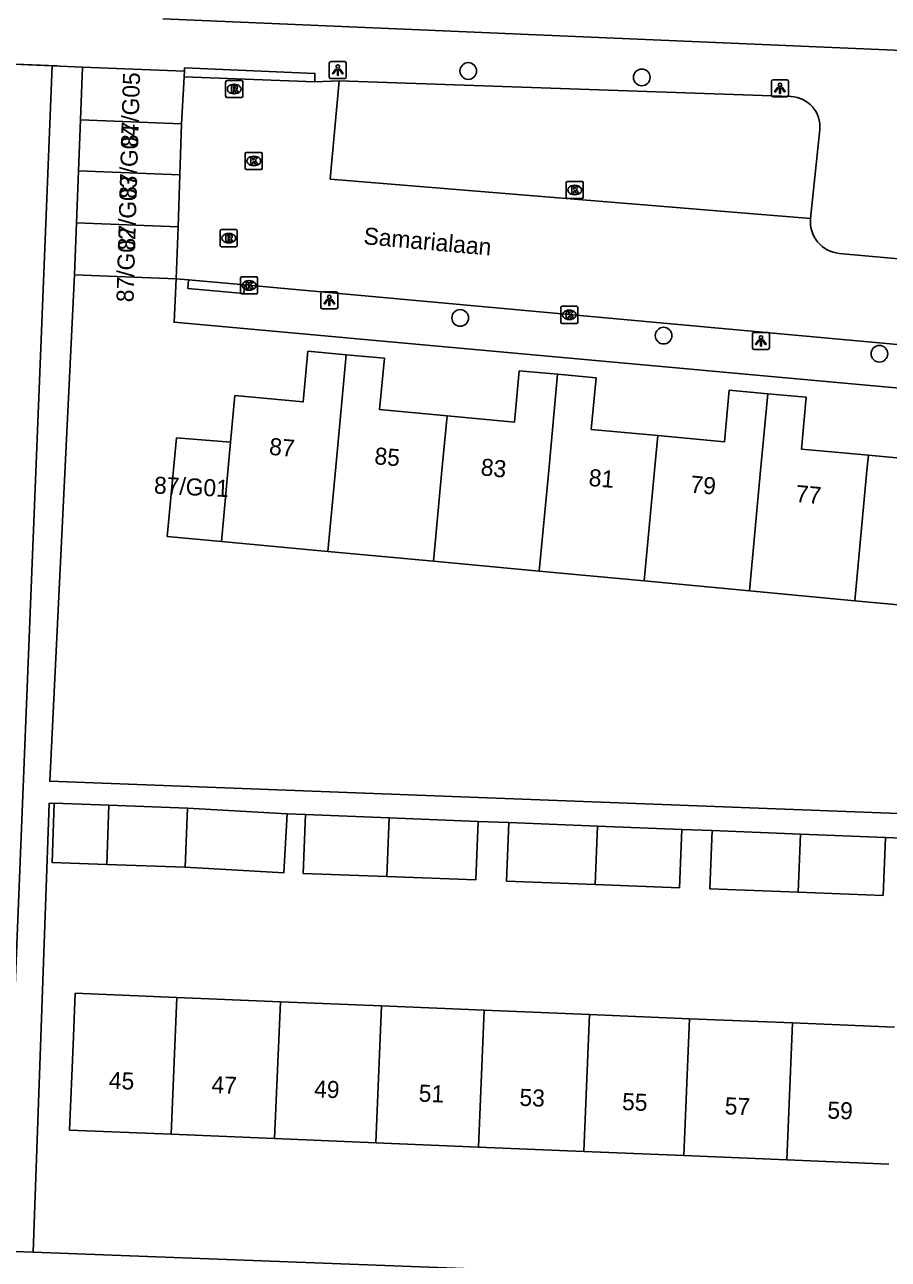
# Model space of a CAD drawing. Extents: x 161355 to 162026, y 386504 to 387459.
# Drawn here: x 161429.3 to 161480, y 386953.7 to 387026.1 of the extents above; entities that cross this region are included whole.
import ezdxf

# ---------------------------------------------------------------- set-up
doc = ezdxf.new("R2010")
doc.units = 0
for name, color, linetype in [('IMGEO_Boom', 7, 'Continuous'), ('IMGEO_Kolk', 7, 'Continuous'), ('IMGEO_Lichtpunt', 7, 'Continuous'), ('IMGEO_Muur', 7, 'Continuous'), ('IMGEO_Openbare_ruimte_label', 7, 'Continuous'), ('IMGEO_Pand', 7, 'Continuous'), ('IMGEO_Pand_nummerreeks', 7, 'Continuous'), ('IMGEO_Rijbaan_lokaal_open', 7, 'Continuous'), ('IMGEO_Rioolput', 7, 'Continuous'), ('IMGEO_Voetpad_open', 7, 'Continuous')]:
    doc.layers.add(name, color=color, linetype=linetype)

msp = doc.modelspace()

# ---------------------------------------------------------------- linework, layer by layer
at = {"layer": 'IMGEO_Boom'}
for centre in [(161455.37, 387023.422), (161465.547, 387023.046), (161454.896, 387008.942), (161466.827, 387007.904), (161479.482, 387006.842)]:
    msp.add_circle(centre, 0.489, dxfattribs=at)
at = {"layer": 'IMGEO_Kolk'}
for p, q in [((161442.286, 387017.721), (161442.286, 387018.573)), ((161442.361, 387018.647), (161443.213, 387018.647)), ((161442.774, 387018.427), (161442.799, 387018.427)), ((161443.287, 387018.573), (161443.287, 387017.721)), ((161443.213, 387017.647), (161442.361, 387017.647)), ((161442.797, 387017.867), (161442.772, 387017.867)), ((161461.114, 387016.016), (161461.114, 387016.868)), ((161461.189, 387016.942), (161462.041, 387016.942)), ((161462.115, 387016.868), (161462.115, 387016.016)), ((161461.625, 387016.162), (161461.6, 387016.162)), ((161461.602, 387016.722), (161461.627, 387016.722)), ((161462.041, 387015.942), (161461.189, 387015.942)), ((161442.01, 387010.423), (161442.01, 387011.275)), ((161442.085, 387011.349), (161442.937, 387011.349)), ((161442.498, 387011.129), (161442.523, 387011.129)), ((161443.011, 387011.275), (161443.011, 387010.423)), ((161442.937, 387010.349), (161442.085, 387010.349)), ((161442.521, 387010.569), (161442.496, 387010.569)), ((161460.795, 387008.698), (161460.795, 387009.55)), ((161460.87, 387009.624), (161461.722, 387009.624)), ((161461.796, 387009.55), (161461.796, 387008.698)), ((161461.306, 387008.844), (161461.281, 387008.844)), ((161461.283, 387009.404), (161461.308, 387009.404)), ((161461.722, 387008.624), (161460.87, 387008.624))]:
    msp.add_line(p, q, dxfattribs=at)
for points in [[(161442.286, 387017.721), (161442.286, 387018.573)], [(161442.361, 387018.647), (161443.213, 387018.647)], [(161442.607, 387018.347), (161442.73, 387018.347), (161442.73, 387018.196), (161442.86, 387018.347), (161443.024, 387018.347), (161442.878, 387018.196), (161443.031, 387017.947), (161442.879, 387017.947), (161442.794, 387018.111), (161442.73, 387018.044), (161442.73, 387017.947), (161442.607, 387017.947), (161442.607, 387018.347)], [(161443.287, 387018.573), (161443.287, 387017.721)], [(161443.213, 387017.647), (161442.361, 387017.647)], [(161461.114, 387016.016), (161461.114, 387016.868)], [(161461.189, 387016.942), (161462.041, 387016.942)], [(161462.115, 387016.868), (161462.115, 387016.016)], [(161461.435, 387016.642), (161461.558, 387016.642), (161461.558, 387016.491), (161461.688, 387016.642), (161461.852, 387016.642), (161461.706, 387016.491), (161461.859, 387016.242), (161461.707, 387016.242), (161461.622, 387016.406), (161461.558, 387016.339), (161461.558, 387016.242), (161461.435, 387016.242), (161461.435, 387016.642)], [(161462.041, 387015.942), (161461.189, 387015.942)], [(161442.01, 387010.423), (161442.01, 387011.275)], [(161442.085, 387011.349), (161442.937, 387011.349)], [(161442.331, 387011.049), (161442.454, 387011.049), (161442.454, 387010.898), (161442.584, 387011.049), (161442.748, 387011.049), (161442.602, 387010.898), (161442.755, 387010.649), (161442.603, 387010.649), (161442.518, 387010.813), (161442.454, 387010.746), (161442.454, 387010.649), (161442.331, 387010.649), (161442.331, 387011.049)], [(161443.011, 387011.275), (161443.011, 387010.423)], [(161442.937, 387010.349), (161442.085, 387010.349)], [(161460.795, 387008.698), (161460.795, 387009.55)], [(161460.87, 387009.624), (161461.722, 387009.624)], [(161461.796, 387009.55), (161461.796, 387008.698)], [(161461.116, 387009.324), (161461.239, 387009.324), (161461.239, 387009.173), (161461.369, 387009.324), (161461.533, 387009.324), (161461.387, 387009.173), (161461.54, 387008.924), (161461.388, 387008.924), (161461.303, 387009.088), (161461.239, 387009.021), (161461.239, 387008.924), (161461.116, 387008.924), (161461.116, 387009.324)], [(161461.722, 387008.624), (161460.87, 387008.624)]]:
    msp.add_lwpolyline(points, dxfattribs=at)
for centre, start, end in [((161442.363, 387018.571), 91.55205, 178.44795), ((161442.363, 387018.571), 91.55205, 178.44795), ((161443.211, 387018.571), 1.55205, 88.44795), ((161443.211, 387018.571), 1.55205, 88.44795), ((161442.363, 387017.723), 181.55205, 268.44795), ((161442.363, 387017.723), 181.55205, 268.44795), ((161443.211, 387017.723), 271.55205, 358.44795), ((161443.211, 387017.723), 271.55205, 358.44795), ((161461.191, 387016.866), 91.55205, 178.44795), ((161461.191, 387016.866), 91.55205, 178.44795), ((161462.039, 387016.866), 1.55205, 88.44795), ((161462.039, 387016.866), 1.55205, 88.44795), ((161461.191, 387016.018), 181.55205, 268.44795), ((161461.191, 387016.018), 181.55205, 268.44795), ((161462.039, 387016.018), 271.55205, 358.44795), ((161462.039, 387016.018), 271.55205, 358.44795), ((161442.087, 387011.273), 91.55205, 178.44795), ((161442.087, 387011.273), 91.55205, 178.44795), ((161442.935, 387011.273), 1.55205, 88.44795), ((161442.935, 387011.273), 1.55205, 88.44795), ((161442.087, 387010.425), 181.55205, 268.44795), ((161442.087, 387010.425), 181.55205, 268.44795), ((161442.935, 387010.425), 271.55205, 358.44795), ((161442.935, 387010.425), 271.55205, 358.44795), ((161460.872, 387009.548), 91.55205, 178.44795), ((161460.872, 387009.548), 91.55205, 178.44795), ((161461.72, 387009.548), 1.55205, 88.44795), ((161461.72, 387009.548), 1.55205, 88.44795), ((161460.872, 387008.7), 181.55205, 268.44795), ((161460.872, 387008.7), 181.55205, 268.44795), ((161461.72, 387008.7), 271.55205, 358.44795), ((161461.72, 387008.7), 271.55205, 358.44795)]:
    msp.add_arc(centre, 0.0765, start, end, dxfattribs=at)
for centre, major_axis, ratio, start_param, end_param in [((161442.773, 387018.147), (-0.387, 0.002), 0.722429, 4.712389, 7.853982), ((161442.798, 387018.147), (-0.39, 0.002), 0.717154, 1.570796, 4.712389), ((161461.601, 387016.442), (-0.387, 0.002), 0.722429, 4.712389, 7.853982), ((161461.626, 387016.442), (-0.39, 0.002), 0.717154, 1.570796, 4.712389), ((161442.497, 387010.849), (-0.387, 0.002), 0.722429, 4.712389, 7.853982), ((161442.522, 387010.849), (-0.39, 0.002), 0.717154, 1.570796, 4.712389), ((161461.282, 387009.124), (-0.387, 0.002), 0.722429, 4.712389, 7.853982), ((161461.307, 387009.124), (-0.39, 0.002), 0.717154, 1.570796, 4.712389)]:
    msp.add_ellipse(centre, major_axis=major_axis, ratio=ratio, start_param=start_param, end_param=end_param, dxfattribs=at)
at = {"layer": 'IMGEO_Lichtpunt'}
for p, q in [((161447.217, 387023.882), (161447.217, 387023.075)), ((161447.217, 387023.882), (161447.217, 387023.075)), ((161448.119, 387023.977), (161447.311, 387023.977)), ((161448.119, 387023.977), (161447.311, 387023.977)), ((161448.213, 387023.075), (161448.213, 387023.882)), ((161448.213, 387023.075), (161448.213, 387023.882)), ((161447.311, 387022.981), (161448.119, 387022.981)), ((161447.311, 387022.981), (161448.119, 387022.981)), ((161473.153, 387022.815), (161473.153, 387022.008)), ((161473.153, 387022.815), (161473.153, 387022.008)), ((161474.055, 387022.91), (161473.247, 387022.91)), ((161474.055, 387022.91), (161473.247, 387022.91)), ((161474.149, 387022.008), (161474.149, 387022.815)), ((161474.149, 387022.008), (161474.149, 387022.815)), ((161473.247, 387021.914), (161474.055, 387021.914)), ((161473.247, 387021.914), (161474.055, 387021.914)), ((161446.721, 387010.38), (161446.721, 387009.573)), ((161446.721, 387010.38), (161446.721, 387009.573)), ((161447.623, 387010.475), (161446.815, 387010.475)), ((161447.623, 387010.475), (161446.815, 387010.475)), ((161447.717, 387009.573), (161447.717, 387010.38)), ((161447.717, 387009.573), (161447.717, 387010.38)), ((161446.815, 387009.479), (161447.623, 387009.479)), ((161446.815, 387009.479), (161447.623, 387009.479)), ((161472.941, 387008.097), (161472.133, 387008.097)), ((161472.941, 387008.097), (161472.133, 387008.097)), ((161472.039, 387008.002), (161472.039, 387007.195)), ((161472.039, 387008.002), (161472.039, 387007.195)), ((161473.035, 387007.195), (161473.035, 387008.002)), ((161473.035, 387007.195), (161473.035, 387008.002)), ((161472.133, 387007.101), (161472.941, 387007.101)), ((161472.133, 387007.101), (161472.941, 387007.101))]:
    msp.add_line(p, q, dxfattribs=at)
for points in [[(161447.591, 387023.546), (161447.63, 387023.518), (161447.442, 387023.256), (161447.404, 387023.283), (161447.591, 387023.546)], [(161447.693, 387023.498), (161447.74, 387023.498), (161447.74, 387023.176), (161447.693, 387023.176), (161447.693, 387023.498)], [(161447.803, 387023.518), (161447.841, 387023.545), (161448.028, 387023.283), (161447.989, 387023.255), (161447.803, 387023.518)], [(161473.527, 387022.479), (161473.566, 387022.451), (161473.378, 387022.189), (161473.34, 387022.216), (161473.527, 387022.479)], [(161473.629, 387022.431), (161473.676, 387022.431), (161473.676, 387022.109), (161473.629, 387022.109), (161473.629, 387022.431)], [(161473.739, 387022.451), (161473.777, 387022.478), (161473.964, 387022.216), (161473.925, 387022.188), (161473.739, 387022.451)], [(161447.095, 387010.044), (161447.134, 387010.016), (161446.946, 387009.754), (161446.908, 387009.781), (161447.095, 387010.044)], [(161447.197, 387009.996), (161447.244, 387009.996), (161447.244, 387009.674), (161447.197, 387009.674), (161447.197, 387009.996)], [(161447.307, 387010.016), (161447.345, 387010.043), (161447.532, 387009.781), (161447.493, 387009.753), (161447.307, 387010.016)], [(161472.413, 387007.666), (161472.452, 387007.638), (161472.264, 387007.376), (161472.226, 387007.403), (161472.413, 387007.666)], [(161472.515, 387007.618), (161472.562, 387007.618), (161472.562, 387007.296), (161472.515, 387007.296), (161472.515, 387007.618)], [(161472.625, 387007.638), (161472.663, 387007.665), (161472.85, 387007.403), (161472.811, 387007.375), (161472.625, 387007.638)]]:
    msp.add_lwpolyline(points, dxfattribs=at)
for centre in [(161447.716, 387023.68), (161473.652, 387022.613), (161447.22, 387010.178), (161472.538, 387007.8)]:
    msp.add_circle(centre, 0.0994, dxfattribs=at)
for centre, start, end in [((161447.311, 387023.882), 90, 180), ((161447.311, 387023.882), 90, 180), ((161448.119, 387023.882), 0, 90), ((161448.119, 387023.882), 0, 90), ((161447.311, 387023.075), 180, 270), ((161447.311, 387023.075), 180, 270), ((161448.119, 387023.075), 270, 0), ((161448.119, 387023.075), 270, 360), ((161473.247, 387022.815), 90, 180), ((161473.247, 387022.815), 90, 180), ((161474.055, 387022.815), 0, 90), ((161474.055, 387022.815), 0, 90), ((161473.247, 387022.008), 180, 270), ((161473.247, 387022.008), 180, 270), ((161474.055, 387022.008), 270, 0), ((161474.055, 387022.008), 270, 360), ((161446.815, 387010.38), 90, 180), ((161446.815, 387010.38), 90, 180), ((161447.623, 387010.38), 0, 90), ((161447.623, 387010.38), 0, 90), ((161446.815, 387009.573), 180, 270), ((161446.815, 387009.573), 180, 270), ((161447.623, 387009.573), 270, 0), ((161447.623, 387009.573), 270, 360), ((161472.133, 387008.002), 90, 180), ((161472.133, 387008.002), 90, 180), ((161472.941, 387008.002), 0, 90), ((161472.941, 387008.002), 0, 90), ((161472.133, 387007.195), 180, 270), ((161472.133, 387007.195), 180, 270), ((161472.941, 387007.195), 270, 0), ((161472.941, 387007.195), 270, 360)]:
    msp.add_arc(centre, 0.0946, start, end, dxfattribs=at)
at = {"layer": 'IMGEO_Muur'}
msp.add_lwpolyline([(161431.241, 387023.718), (161424.947, 387023.983)], dxfattribs=at)
at = {"layer": 'IMGEO_Pand'}
for points in [[(161432.74, 387023.655), (161432.618, 387020.553)], [(161438.717, 387023.42), (161432.74, 387023.655)], [(161438.717, 387023.42), (161438.699, 387023.089)], [(161438.699, 387023.089), (161438.547, 387020.324)], [(161432.618, 387020.553), (161432.501, 387017.566)], [(161432.618, 387020.553), (161438.547, 387020.324)], [(161438.547, 387020.324), (161438.453, 387017.332)], [(161432.381, 387014.522), (161432.501, 387017.566)], [(161432.501, 387017.566), (161438.453, 387017.332)], [(161438.453, 387017.332), (161438.358, 387014.287)], [(161432.381, 387014.522), (161432.262, 387011.478)], [(161438.358, 387014.287), (161432.381, 387014.522)], [(161438.358, 387014.287), (161438.239, 387011.243)], [(161432.262, 387011.478), (161438.239, 387011.243)], [(161441.431, 387001.649), (161441.685, 387004.394), (161445.688, 387004.023), (161445.963, 387006.992), (161448.208, 387006.784)], [(161448.208, 387006.784), (161447.574, 387000), (161447.13, 386995.256)], [(161454.125, 387003.206), (161450.171, 387003.572), (161450.45, 387006.576), (161448.208, 387006.784)], [(161460.612, 387005.637), (161458.361, 387005.845), (161458.082, 387002.839), (161454.125, 387003.206)], [(161459.533, 386994.096), (161460.085, 387000), (161460.612, 387005.637)], [(161466.49, 387002.046), (161462.585, 387002.408), (161462.865, 387005.428), (161460.612, 387005.637)], [(161466.49, 387002.046), (161470.397, 387001.684), (161470.678, 387004.71), (161472.935, 387004.5)], [(161472.935, 387004.5), (161472.515, 387000), (161471.855, 386992.943)], [(161472.935, 387004.5), (161475.192, 387004.291), (161474.91, 387001.252), (161478.838, 387000.888)], [(161453.328, 386994.676), (161453.826, 387000), (161454.125, 387003.206)], [(161485.285, 387003.307), (161483.042, 387003.514), (161482.765, 387000.524), (161478.838, 387000.888)], [(161440.89, 386995.839), (161437.709, 386996.137), (161438.259, 387001.907), (161441.431, 387001.649)], [(161441.431, 387001.649), (161440.89, 386995.839)], [(161465.693, 386993.519), (161466.299, 387000), (161466.49, 387002.046)], [(161478.838, 387000.888), (161478.755, 387000), (161478.041, 386992.364)], [(161447.13, 386995.256), (161440.89, 386995.839)], [(161447.13, 386995.256), (161453.328, 386994.676)], [(161453.328, 386994.676), (161459.533, 386994.096)], [(161459.533, 386994.096), (161465.693, 386993.519)], [(161471.855, 386992.943), (161465.693, 386993.519)], [(161478.041, 386992.364), (161471.855, 386992.943)], [(161478.041, 386992.364), (161484.208, 386991.788)], [(161434.159, 386976.895), (161430.959, 386977.014), (161431.087, 386980.484)], [(161431.087, 386980.484), (161434.288, 386980.365)], [(161434.288, 386980.365), (161434.159, 386976.895)], [(161434.288, 386980.365), (161438.896, 386980.191)], [(161438.753, 386976.737), (161438.896, 386980.191)], [(161444.745, 386979.866), (161444.553, 386976.414), (161438.753, 386976.737)], [(161438.896, 386980.191), (161444.745, 386979.866)], [(161445.828, 386979.823), (161445.685, 386976.371), (161450.594, 386976.186)], [(161445.828, 386979.823), (161450.736, 386979.63)], [(161450.736, 386979.63), (161450.594, 386976.186)], [(161450.594, 386976.186), (161455.805, 386975.989), (161455.946, 386979.424)], [(161455.946, 386979.424), (161450.736, 386979.63)], [(161457.753, 386979.353), (161457.611, 386975.92), (161462.805, 386975.724)], [(161462.946, 386979.148), (161457.753, 386979.353)], [(161462.946, 386979.148), (161462.805, 386975.724)], [(161467.901, 386978.953), (161462.946, 386979.148)], [(161462.805, 386975.724), (161467.76, 386975.536), (161467.901, 386978.953)], [(161469.673, 386978.883), (161469.531, 386975.469), (161474.71, 386975.274)], [(161474.851, 386978.679), (161469.673, 386978.883)], [(161474.851, 386978.679), (161474.71, 386975.274)], [(161474.71, 386975.274), (161479.704, 386975.085), (161479.844, 386978.482)], [(161479.844, 386978.482), (161474.851, 386978.679)], [(161434.159, 386976.895), (161438.753, 386976.737)], [(161438.272, 386969.101), (161432.314, 386969.348), (161432.188, 386966.317), (161431.981, 386961.321), (161437.939, 386961.074)], [(161437.939, 386961.074), (161438.272, 386969.101)], [(161444.345, 386968.849), (161438.272, 386969.101)], [(161444.345, 386968.849), (161444.012, 386960.822)], [(161450.279, 386968.603), (161444.345, 386968.849)], [(161449.946, 386960.576), (161450.279, 386968.603)], [(161450.279, 386968.603), (161456.306, 386968.353)], [(161456.306, 386968.353), (161455.973, 386960.326)], [(161462.488, 386968.097), (161456.306, 386968.353)], [(161462.155, 386960.07), (161462.488, 386968.097)], [(161468.353, 386967.854), (161462.488, 386968.097)], [(161468.353, 386967.854), (161468.021, 386959.826)], [(161474.393, 386967.604), (161468.353, 386967.854)], [(161474.061, 386959.576), (161474.393, 386967.604)], [(161480.376, 386967.356), (161474.393, 386967.604)], [(161437.939, 386961.074), (161444.012, 386960.822)], [(161444.012, 386960.822), (161449.946, 386960.576)], [(161455.973, 386960.326), (161449.946, 386960.576)], [(161455.973, 386960.326), (161462.155, 386960.07)], [(161462.155, 386960.07), (161468.021, 386959.826)], [(161468.021, 386959.826), (161474.061, 386959.576)], [(161474.061, 386959.576), (161480.043, 386959.328)]]:
    msp.add_lwpolyline(points, dxfattribs=at)
at = {"layer": 'IMGEO_Rijbaan_lokaal_open'}
for points in [[(161446.36, 387022.778), (161438.699, 387023.089)], [(161447.79, 387022.848), (161446.36, 387022.778)], [(161447.79, 387022.848), (161447.27, 387017.085), (161475.445, 387014.773)], [(161506.058, 387010.118), (161500, 387010.665), (161477.129, 387012.73)], [(161438.965, 387011.176), (161438.239, 387011.243)], [(161438.965, 387011.176), (161442.235, 387010.876)], [(161505.887, 387005.07), (161500, 387005.605), (161442.235, 387010.876)]]:
    msp.add_lwpolyline(points, dxfattribs=at)
msp.add_arc((161477.296, 387014.583), 1.861, 174.14879, 264.84723, dxfattribs=at)
at = {"layer": 'IMGEO_Rioolput'}
for p, q in [((161441.138, 387021.938), (161441.138, 387022.79)), ((161441.213, 387022.864), (161442.065, 387022.864)), ((161441.626, 387022.644), (161441.651, 387022.644)), ((161442.139, 387022.79), (161442.139, 387021.938)), ((161442.065, 387021.864), (161441.213, 387021.864)), ((161441.649, 387022.084), (161441.624, 387022.084)), ((161440.82, 387013.194), (161440.82, 387014.046)), ((161440.895, 387014.12), (161441.747, 387014.12)), ((161441.308, 387013.9), (161441.333, 387013.9)), ((161441.821, 387014.046), (161441.821, 387013.194)), ((161441.331, 387013.34), (161441.306, 387013.34)), ((161441.747, 387013.12), (161440.895, 387013.12))]:
    msp.add_line(p, q, dxfattribs=at)
for points in [[(161441.138, 387021.938), (161441.138, 387022.79)], [(161441.213, 387022.864), (161442.065, 387022.864)], [(161441.727, 387022.562), (161441.475, 387022.564), (161441.475, 387022.164)], [(161442.139, 387022.79), (161442.139, 387021.938)], [(161442.065, 387021.864), (161441.213, 387021.864)], [(161441.475, 387022.164), (161441.599, 387022.164), (161441.599, 387022.326), (161441.61, 387022.326)], [(161441.653, 387022.483), (161441.599, 387022.483), (161441.599, 387022.402)], [(161441.599, 387022.402), (161441.651, 387022.402)], [(161441.657, 387022.297), (161441.728, 387022.164), (161441.868, 387022.164), (161441.803, 387022.29)], [(161440.82, 387013.194), (161440.82, 387014.046)], [(161440.895, 387014.12), (161441.747, 387014.12)], [(161441.821, 387014.046), (161441.821, 387013.194)], [(161441.409, 387013.818), (161441.157, 387013.82), (161441.157, 387013.42)], [(161441.157, 387013.42), (161441.281, 387013.42), (161441.281, 387013.582), (161441.292, 387013.582)], [(161441.335, 387013.739), (161441.281, 387013.739), (161441.281, 387013.658)], [(161441.281, 387013.658), (161441.333, 387013.658)], [(161441.339, 387013.553), (161441.41, 387013.42), (161441.55, 387013.42), (161441.485, 387013.546)], [(161441.747, 387013.12), (161440.895, 387013.12)]]:
    msp.add_lwpolyline(points, dxfattribs=at)
for centre, radius, start, end in [((161441.215, 387022.788), 0.0765, 91.55205, 178.44795), ((161441.215, 387022.788), 0.0765, 91.55205, 178.44795), ((161441.726, 387022.452), 0.109, 350.36119, 89.41601), ((161442.063, 387022.788), 0.0765, 1.55205, 88.44795), ((161442.063, 387022.788), 0.0765, 1.55205, 88.44795), ((161441.215, 387021.94), 0.0765, 181.55205, 268.44795), ((161441.215, 387021.94), 0.0765, 181.55205, 268.44795), ((161441.609, 387022.273), 0.0533, 26.02933, 88.69889), ((161441.635, 387022.591), 0.19, 274.7715, 282.96867), ((161441.659, 387022.387), 0.0964, 77.00612, 93.18647), ((161441.673, 387022.444), 0.0378, 276.66336, 79.67722), ((161441.724, 387022.452), 0.112, 277.58423, 350.98172), ((161441.708, 387022.237), 0.108, 29.51342, 73.79051), ((161442.063, 387021.94), 0.0765, 271.55205, 358.44795), ((161442.063, 387021.94), 0.0765, 271.55205, 358.44795), ((161440.897, 387014.044), 0.0765, 91.55205, 178.44795), ((161440.897, 387014.044), 0.0765, 91.55205, 178.44795), ((161441.745, 387014.044), 0.0765, 1.55205, 88.44795), ((161441.745, 387014.044), 0.0765, 1.55205, 88.44795), ((161440.897, 387013.196), 0.0765, 181.55205, 268.44795), ((161440.897, 387013.196), 0.0765, 181.55205, 268.44795), ((161441.291, 387013.529), 0.0533, 26.02933, 88.69889), ((161441.317, 387013.847), 0.19, 274.7715, 282.96867), ((161441.341, 387013.643), 0.0964, 77.00612, 93.18647), ((161441.355, 387013.7), 0.0378, 276.66336, 79.67722), ((161441.408, 387013.708), 0.109, 350.36119, 89.41601), ((161441.406, 387013.708), 0.112, 277.58423, 350.98172), ((161441.39, 387013.493), 0.108, 29.51342, 73.79051), ((161441.745, 387013.196), 0.0765, 271.55205, 358.44795), ((161441.745, 387013.196), 0.0765, 271.55205, 358.44795)]:
    msp.add_arc(centre, radius, start, end, dxfattribs=at)
for centre, major_axis, ratio, start_param, end_param in [((161441.625, 387022.364), (-0.387, 0.002), 0.722429, 4.712389, 7.853982), ((161441.65, 387022.364), (-0.39, 0.002), 0.717154, 1.570796, 4.712389), ((161441.307, 387013.62), (-0.387, 0.002), 0.722429, 4.712389, 7.853982), ((161441.332, 387013.62), (-0.39, 0.002), 0.717154, 1.570796, 4.712389)]:
    msp.add_ellipse(centre, major_axis=major_axis, ratio=ratio, start_param=start_param, end_param=end_param, dxfattribs=at)
at = {"layer": 'IMGEO_Voetpad_open'}
for points in [[(161504.653, 387023.606), (161500, 387023.805), (161437.454, 387026.478)], [(161430.964, 387023.73), (161424.947, 387023.983), (161421.554, 387024.126), (161410.63, 387024.386)], [(161428.171, 386954.217), (161430.964, 387023.73)], [(161430.964, 387023.73), (161432.74, 387023.655)], [(161446.36, 387022.778), (161446.373, 387023.277), (161438.722, 387023.6), (161438.717, 387023.42)], [(161474.31, 387021.919), (161447.79, 387022.848)], [(161475.445, 387014.773), (161475.982, 387019.984)], [(161499.085, 386979.191), (161430.824, 386981.776), (161432.262, 387011.478)], [(161438.239, 387011.243), (161438.114, 387008.687), (161500, 387003.064), (161504.372, 387002.667)], [(161442.235, 387010.876), (161442.198, 387010.378), (161438.928, 387010.678), (161438.965, 387011.176)], [(161429.855, 386954.16), (161430.784, 386980.481), (161431.087, 386980.484)], [(161444.745, 386979.866), (161445.828, 386979.823)], [(161455.946, 386979.424), (161457.753, 386979.353)], [(161467.901, 386978.953), (161469.673, 386978.883)], [(161479.844, 386978.482), (161481.796, 386978.405)], [(161429.855, 386954.16), (161428.171, 386954.217)], [(161502.002, 386951.426), (161500, 386951.511), (161429.855, 386954.16)]]:
    msp.add_lwpolyline(points, dxfattribs=at)
msp.add_arc((161474.236, 387020.165), 1.756, 354.08157, 87.57789, dxfattribs=at)

# ---------------------------------------------------------------- texts
at = {"layer": 'IMGEO_Openbare_ruimte_label'}
msp.add_text('Samarialaan', height=1, rotation=354.83669, dxfattribs=at).set_placement((161449.2, 387013.271))
at = {"layer": 'IMGEO_Pand_nummerreeks'}
for s, rotation, p in [('87/G05', 88.3329, (161435.994, 387018.945)), ('87/G04', 88.33489, (161435.906, 387015.917)), ('87/G03', 88.33489, (161435.818, 387012.889)), ('87/G02', 88.33489, (161435.73, 387009.854)), ('87', 354.87859, (161443.658, 387000.924)), ('85', 354.87859, (161449.834, 387000.37)), ('83', 354.31322, (161456.066, 386999.718)), ('87/G01', 357.27369, (161436.917, 386998.645)), ('81', 355.20995, (161462.404, 386999.098)), ('79', 354.87859, (161468.365, 386998.709)), ('77', 354.87859, (161474.542, 386998.156)), ('45', 357.6255, (161434.271, 386963.749)), ('47', 357.6255, (161440.292, 386963.499)), ('49', 357.6255, (161446.312, 386963.249)), ('51', 357.6255, (161452.446, 386962.995)), ('53', 357.6255, (161458.354, 386962.75)), ('55', 357.6255, (161464.375, 386962.5)), ('57', 357.6255, (161470.396, 386962.251)), ('59', 357.6255, (161476.417, 386962.001))]:
    msp.add_text(s, height=1, rotation=rotation, dxfattribs=at).set_placement(p)

doc.saveas('drawing.dxf')
